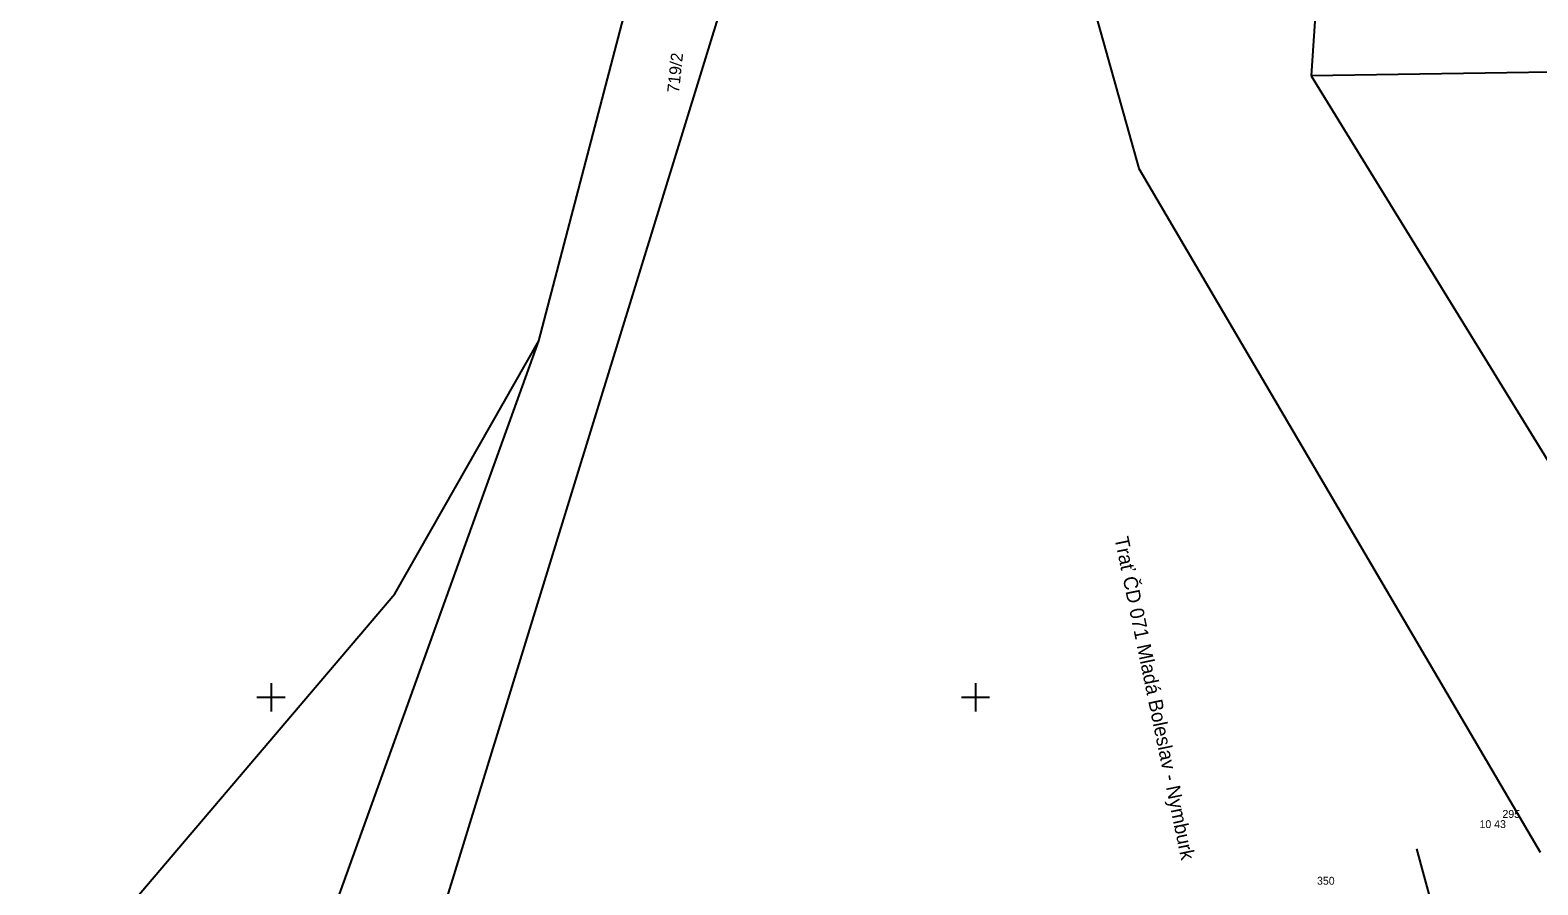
# Model space of a CAD drawing. Extents: x -703403 to -701924, y -1022520 to -1021856.
# Drawn here: x -702358.6 to -702305, y -1022256.7 to -1022226.3 of the extents above; entities that cross this region are included whole.
import ezdxf

# ---------------------------------------------------------------- set-up
doc = ezdxf.new("R2010")
doc.units = 0
for name, color, linetype in [('Ex_Minor Contours', 7, 'Continuous'), ('Z_body', 7, 'Continuous'), ('Z_body_cisla', 7, 'Continuous'), ('Z_body_vysky_redukovane', 7, 'Continuous'), ('Z_hektometricka_sit', 7, 'Continuous'), ('Z_katastr_cisla_pozemkova', 7, 'Continuous'), ('Z_katastr_hranice', 7, 'Continuous'), ('Z_popisy', 7, 'Continuous')]:
    doc.layers.add(name, color=color, linetype=linetype)

# ---------------------------------------------------------------- blocks, each defined once
blk = doc.blocks.new('POINT_DISPLAY')
blk.add_line((0, 0), (0, 0))

msp = doc.modelspace()

# ---------------------------------------------------------------- linework, layer by layer
at = {"layer": 'Ex_Minor Contours'}
msp.add_lwpolyline([(-702309.346, -1022255.376), (-702308.794, -1022257.425)], dxfattribs=at)
at = {"layer": 'Z_hektometricka_sit'}
for p, q in [((-702350, -1022249.5), (-702350, -1022250.5)), ((-702325, -1022249.5), (-702325, -1022250.5)), ((-702350.5, -1022250), (-702349.5, -1022250)), ((-702325.5, -1022250), (-702324.5, -1022250))]:
    msp.add_line(p, q, dxfattribs=at)
at = {"layer": 'Z_katastr_hranice'}
for p, q in [((-702309.8, -1022178.46), (-702313.09, -1022227.94)), ((-702324.74, -1022211.47), (-702319.2, -1022231.23)), ((-702340.5, -1022237.35), (-702335.97, -1022220.06)), ((-702349.19, -1022274.77), (-702332.69, -1022221.19)), ((-702279.99, -1022227.44), (-702313.09, -1022227.94)), ((-702313.09, -1022227.94), (-702298.93, -1022250.97)), ((-702319.2, -1022231.23), (-702304.96, -1022255.49)), ((-702352.7, -1022271.24), (-702340.5, -1022237.35)), ((-702345.61, -1022246.33), (-702340.5, -1022237.35)), ((-702358.55, -1022261.54), (-702345.61, -1022246.33))]:
    msp.add_line(p, q, dxfattribs=at)

# ---------------------------------------------------------------- block references
at = {"layer": 'Z_body'}
msp.add_blockref('POINT_DISPLAY', (-702306.53, -1022254.36), dxfattribs=at)

# ---------------------------------------------------------------- texts
at = {"layer": 'Z_body_cisla'}
for s, p in [('295', (-702306.3, -1022254.28)), ('350', (-702312.88, -1022256.65))]:
    msp.add_text(s, height=0.28, dxfattribs=at).set_placement(p)
at = {"layer": 'Z_body_vysky_redukovane'}
msp.add_text('10 43', height=0.28, dxfattribs=at).set_placement((-702307.113, -1022254.64))
at = {"layer": 'Z_katastr_cisla_pozemkova'}
msp.add_text('719/2', height=0.425, rotation=84, dxfattribs=at).set_placement((-702335.524, -1022228.563))
at = {"layer": 'Z_popisy'}
msp.add_text('Trať ČD 071 Mladá Boleslav - Nymburk', height=0.5, rotation=281.7, dxfattribs=at).set_placement((-702320.07, -1022244.35))

doc.saveas('drawing.dxf')
